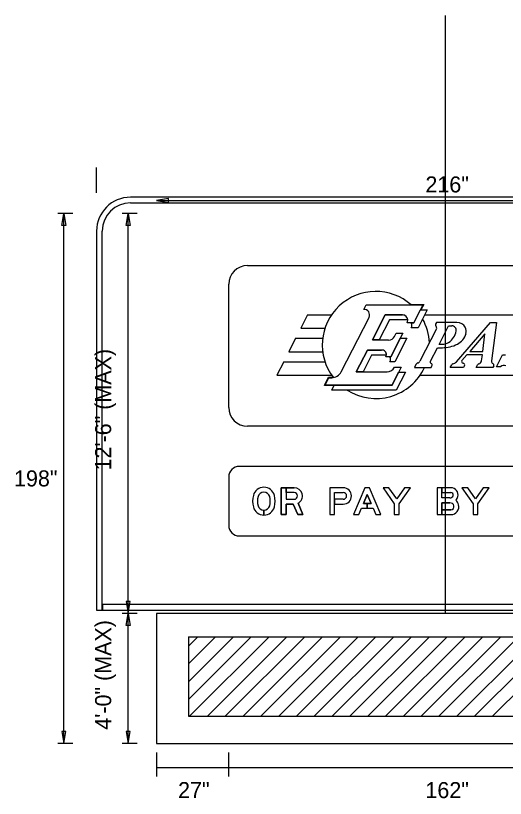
# Model space of a CAD drawing. Extents: x 10268312 to 10268706, y 2142548 to 2142786.
# Drawn here: x 10268428.63 to 10268450.13, y 2142751.91 to 2142786.29 of the extents above; entities that cross this region are included whole.
import ezdxf

# ---------------------------------------------------------------- set-up
doc = ezdxf.new("R2010")
doc.units = 0
for name, color, linetype in [('GSBWFill', 7, 'Continuous'), ('GSDims', 7, 'Continuous'), ('SignPanel', 7, 'Continuous'), ('TextMisc', 7, 'Continuous')]:
    doc.layers.add(name, color=color, linetype=linetype)

msp = doc.modelspace()

# ---------------------------------------------------------------- linework, layer by layer
at = {"layer": 'GSBWFill'}
for p, q in [((10268432.186, 2142778.502), (10268432.186, 2142779.616)), ((10268457.439, 2142778.317), (10268433.672, 2142778.317)), ((10268433.672, 2142778.069), (10268457.439, 2142778.069))]:
    msp.add_line(p, q, dxfattribs=at)
for points in [[(10268432.186, 2142776.831), (10268432.186, 2142760.182), (10268432.434, 2142760.182), (10268432.434, 2142776.831)], [(10268458.676, 2142760.43), (10268432.441, 2142760.43), (10268432.441, 2142760.182), (10268458.924, 2142760.182), (10268458.924, 2142760.182), (10268458.924, 2142776.831)]]:
    msp.add_lwpolyline(points, dxfattribs=at)
for radius in [1.485, 1.238]:
    msp.add_arc((10268433.672, 2142776.831), radius, 90, 180, dxfattribs=at)
at = {"layer": 'GSDims'}
for p, q in [((10268434.809, 2142778.177), (10268460.21, 2142778.177)), ((10268431.138, 2142777.605), (10268430.477, 2142777.605)), ((10268430.741, 2142754.321), (10268430.741, 2142777.605)), ((10268433.97, 2142777.605), (10268433.309, 2142777.605)), ((10268433.573, 2142760.024), (10268433.573, 2142777.605)), ((10268433.97, 2142760.024), (10268433.309, 2142760.024)), ((10268433.573, 2142754.321), (10268433.573, 2142760.024)), ((10268431.138, 2142754.321), (10268430.477, 2142754.321)), ((10268433.97, 2142754.321), (10268433.309, 2142754.321)), ((10268434.809, 2142753.924), (10268434.809, 2142752.865)), ((10268437.984, 2142753.924), (10268437.984, 2142752.865)), ((10268434.809, 2142753.262), (10268437.984, 2142753.262)), ((10268437.984, 2142753.262), (10268457.035, 2142753.262))]:
    msp.add_line(p, q, dxfattribs=at)
for points in [[(10268434.809, 2142778.177), (10268435.338, 2142778.089), (10268435.338, 2142778.265)], [(10268430.741, 2142777.605), (10268430.83, 2142777.075), (10268430.653, 2142777.075)], [(10268433.573, 2142777.605), (10268433.661, 2142777.075), (10268433.485, 2142777.075)], [(10268433.573, 2142760.024), (10268433.661, 2142760.553), (10268433.485, 2142760.553)], [(10268433.573, 2142760.024), (10268433.661, 2142759.495), (10268433.485, 2142759.495)], [(10268430.741, 2142754.321), (10268430.83, 2142754.85), (10268430.653, 2142754.85)], [(10268433.573, 2142754.321), (10268433.661, 2142754.85), (10268433.485, 2142754.85)]]:
    msp.add_lwpolyline(points, close=True, dxfattribs=at)
at = {"layer": 'SignPanel'}
for p, q in [((10268447.509, 2142760.024), (10268447.509, 2142786.291)), ((10268438.809, 2142775.312), (10268456.209, 2142775.312)), ((10268437.986, 2142769.081), (10268437.986, 2142774.489)), ((10268445.977, 2142773.609), (10268446.549, 2142773.609)), ((10268446.549, 2142773.609), (10268446.426, 2142773.366)), ((10268443.915, 2142773.389), (10268444.015, 2142773.587)), ((10268444.015, 2142773.587), (10268446.514, 2142773.587)), ((10268446.113, 2142772.8), (10268446.401, 2142773.366)), ((10268446.514, 2142773.587), (10268446.114, 2142772.801)), ((10268446.698, 2142773.366), (10268446.298, 2142772.58)), ((10268446.401, 2142773.366), (10268446.698, 2142773.366)), ((10268441.449, 2142773.146), (10268441.15, 2142772.558)), ((10268441.449, 2142773.146), (10268442.503, 2142773.146)), ((10268442.927, 2142770.644), (10268444.147, 2142773.037)), ((10268444.862, 2142773.146), (10268444.3, 2142772.044)), ((10268444.3, 2142772.044), (10268444.862, 2142773.146)), ((10268445.047, 2142772.925), (10268444.597, 2142772.044)), ((10268445.611, 2142773.146), (10268444.862, 2142773.146)), ((10268444.862, 2142773.146), (10268445.611, 2142773.146)), ((10268445.846, 2142772.925), (10268445.047, 2142772.925)), ((10268446.586, 2142773.146), (10268454.969, 2142773.146)), ((10268446.114, 2142772.801), (10268445.819, 2142772.801)), ((10268446.004, 2142772.8), (10268446.113, 2142772.8)), ((10268446.298, 2142772.58), (10268446.004, 2142772.58)), ((10268447.107, 2142772.815), (10268447.067, 2142772.737)), ((10268448.007, 2142772.815), (10268447.107, 2142772.815)), ((10268447.222, 2142771.852), (10268447.638, 2142772.668)), ((10268447.222, 2142771.852), (10268447.638, 2142772.668)), ((10268447.638, 2142772.668), (10268447.779, 2142772.668)), ((10268447.638, 2142772.668), (10268447.779, 2142772.668)), ((10268447.984, 2142771.089), (10268449.485, 2142772.815)), ((10268449.485, 2142772.815), (10268449.749, 2142772.815)), ((10268449.749, 2142772.815), (10268449.529, 2142771.124)), ((10268441.15, 2142772.558), (10268442.213, 2142772.558)), ((10268445.627, 2142772.338), (10268445.103, 2142771.309)), ((10268445.265, 2142772.204), (10268445.333, 2142772.338)), ((10268445.333, 2142772.338), (10268445.627, 2142772.338)), ((10268447.109, 2142772.537), (10268446.382, 2142771.109)), ((10268449.239, 2142772.308), (10268448.568, 2142771.536)), ((10268449.239, 2142772.308), (10268448.568, 2142771.536)), ((10268449.138, 2142771.536), (10268449.239, 2142772.308)), ((10268449.138, 2142771.536), (10268449.239, 2142772.308)), ((10268440.925, 2142772.117), (10268440.626, 2142771.529)), ((10268440.925, 2142772.117), (10268442.114, 2142772.117)), ((10268444.3, 2142772.044), (10268445.004, 2142772.044)), ((10268444.597, 2142772.044), (10268444.3, 2142772.044)), ((10268445.103, 2142771.309), (10268445.515, 2142772.117)), ((10268445.812, 2142772.117), (10268445.288, 2142771.088)), ((10268445.515, 2142772.117), (10268445.812, 2142772.117)), ((10268444.076, 2142771.603), (10268443.589, 2142770.647)), ((10268443.589, 2142770.647), (10268444.076, 2142771.603)), ((10268444.721, 2142771.603), (10268444.076, 2142771.603)), ((10268444.076, 2142771.603), (10268444.693, 2142771.601)), ((10268446.843, 2142771.109), (10268447.147, 2142771.705)), ((10268447.147, 2142771.705), (10268447.367, 2142771.705)), ((10268447.367, 2142771.852), (10268447.222, 2142771.852)), ((10268447.367, 2142771.852), (10268447.222, 2142771.852)), ((10268448.568, 2142771.536), (10268449.138, 2142771.536)), ((10268448.568, 2142771.536), (10268449.138, 2142771.536)), ((10268440.626, 2142771.529), (10268442.114, 2142771.529)), ((10268444.26, 2142771.382), (10268443.886, 2142770.647)), ((10268444.909, 2142771.38), (10268444.26, 2142771.382)), ((10268445.103, 2142771.309), (10268444.882, 2142771.309)), ((10268445.057, 2142771.309), (10268445.103, 2142771.309)), ((10268448.44, 2142771.389), (10268448.227, 2142771.145)), ((10268449.123, 2142771.389), (10268448.44, 2142771.389)), ((10268449.089, 2142771.124), (10268449.123, 2142771.389)), ((10268449.748, 2142770.868), (10268450.015, 2142771.392)), ((10268450.015, 2142771.392), (10268450.133, 2142771.392)), ((10268440.402, 2142771.088), (10268440.102, 2142770.5)), ((10268440.402, 2142771.088), (10268442.213, 2142771.088)), ((10268445.288, 2142771.088), (10268445.067, 2142771.088)), ((10268445.558, 2142770.845), (10268445.157, 2142770.06)), ((10268445.264, 2142770.845), (10268445.558, 2142770.845)), ((10268446.203, 2142770.961), (10268446.137, 2142770.831)), ((10268446.872, 2142770.831), (10268446.912, 2142770.91)), ((10268447.714, 2142770.831), (10268447.778, 2142770.957)), ((10268448.345, 2142770.916), (10268448.302, 2142770.831)), ((10268448.848, 2142770.831), (10268448.913, 2142770.959)), ((10268449.621, 2142770.907), (10268449.583, 2142770.831)), ((10268449.927, 2142770.868), (10268449.748, 2142770.868)), ((10268440.102, 2142770.5), (10268442.503, 2142770.5)), ((10268443.589, 2142770.647), (10268444.938, 2142770.647)), ((10268443.886, 2142770.647), (10268443.589, 2142770.647)), ((10268445.157, 2142770.06), (10268445.445, 2142770.625)), ((10268445.742, 2142770.625), (10268445.342, 2142769.839)), ((10268445.445, 2142770.625), (10268445.742, 2142770.625)), ((10268446.137, 2142770.831), (10268446.872, 2142770.831)), ((10268446.391, 2142770.5), (10268453.621, 2142770.5)), ((10268448.302, 2142770.831), (10268447.714, 2142770.831)), ((10268449.583, 2142770.831), (10268448.848, 2142770.831)), ((10268442.187, 2142770.04), (10268442.373, 2142770.406)), ((10268442.218, 2142770.06), (10268442.385, 2142770.387)), ((10268442.373, 2142770.406), (10268442.508, 2142770.406)), ((10268442.385, 2142770.387), (10268442.508, 2142770.387)), ((10268442.615, 2142770.04), (10268442.187, 2142770.04)), ((10268445.157, 2142770.06), (10268442.218, 2142770.06)), ((10268442.512, 2142769.839), (10268442.624, 2142770.06)), ((10268445.342, 2142769.839), (10268442.512, 2142769.839)), ((10268442.624, 2142770.06), (10268445.157, 2142770.06)), ((10268456.209, 2142768.258), (10268438.809, 2142768.258)), ((10268456.562, 2142766.492), (10268438.457, 2142766.492)), ((10268437.986, 2142766.021), (10268437.986, 2142763.905)), ((10268442.635, 2142765.339), (10268443.017, 2142765.339)), ((10268442.635, 2142765.339), (10268443.017, 2142765.339)), ((10268442.635, 2142765.339), (10268443.017, 2142765.339)), ((10268442.635, 2142764.834), (10268443.017, 2142764.834)), ((10268439.53, 2142764.354), (10268439.53, 2142764.566)), ((10268439.53, 2142764.566), (10268439.53, 2142764.354)), ((10268439.53, 2142764.354), (10268439.53, 2142764.566)), ((10268439.53, 2142764.566), (10268439.53, 2142764.354)), ((10268447.139, 2142764.375), (10268447.744, 2142764.375)), ((10268438.457, 2142763.434), (10268456.558, 2142763.434)), ((10268460.21, 2142760.024), (10268434.809, 2142760.024)), ((10268434.809, 2142760.024), (10268434.809, 2142754.321)), ((10268434.809, 2142754.321), (10268460.21, 2142754.321))]:
    msp.add_line(p, q, dxfattribs=at)
for points in [[(10268440.863, 2142765.551), (10268440.295, 2142765.551), (10268440.295, 2142764.375), (10268440.506, 2142764.375), (10268440.506, 2142764.834), (10268440.818, 2142764.834), (10268441.017, 2142764.375), (10268441.247, 2142764.375), (10268441.031, 2142764.875)], [(10268441.031, 2142764.875), (10268441.247, 2142764.375), (10268441.017, 2142764.375), (10268440.818, 2142764.834), (10268440.506, 2142764.834), (10268440.506, 2142764.375), (10268440.295, 2142764.375), (10268440.295, 2142765.551), (10268440.506, 2142765.551), (10268440.506, 2142765.045), (10268440.863, 2142765.045)], [(10268441.031, 2142764.875), (10268441.247, 2142764.375), (10268441.017, 2142764.375), (10268440.818, 2142764.834), (10268440.506, 2142764.834), (10268440.506, 2142764.375), (10268440.295, 2142764.375), (10268440.295, 2142765.551), (10268440.506, 2142765.551), (10268440.506, 2142765.045), (10268440.863, 2142765.045)], [(10268440.506, 2142765.339), (10268440.506, 2142765.551), (10268440.863, 2142765.551)], [(10268440.506, 2142765.339), (10268440.506, 2142765.551), (10268440.863, 2142765.551)], [(10268443.017, 2142765.551), (10268442.423, 2142765.551), (10268442.423, 2142764.375), (10268442.635, 2142764.375), (10268442.635, 2142764.834)], [(10268443.017, 2142765.551), (10268442.423, 2142765.551), (10268442.423, 2142764.375), (10268442.635, 2142764.375), (10268442.635, 2142765.339)], [(10268443.017, 2142765.551), (10268442.423, 2142765.551), (10268442.423, 2142764.375), (10268442.635, 2142764.375), (10268442.635, 2142765.339)], [(10268447.744, 2142765.551), (10268447.139, 2142765.551), (10268447.139, 2142764.375)], [(10268447.699, 2142765.104), (10268447.35, 2142765.104), (10268447.35, 2142765.551), (10268447.139, 2142765.551), (10268447.139, 2142764.375), (10268447.35, 2142764.375)], [(10268447.699, 2142765.104), (10268447.35, 2142765.104), (10268447.35, 2142765.551), (10268447.139, 2142765.551), (10268447.139, 2142764.375), (10268447.35, 2142764.375)], [(10268447.744, 2142765.551), (10268447.351, 2142765.551), (10268447.351, 2142765.339), (10268447.744, 2142765.339)], [(10268447.744, 2142765.551), (10268447.351, 2142765.551), (10268447.351, 2142765.339), (10268447.744, 2142765.339)], [(10268440.863, 2142765.339), (10268440.506, 2142765.339), (10268440.506, 2142765.045), (10268440.863, 2142765.045)], [(10268440.863, 2142765.339), (10268440.506, 2142765.339)], [(10268440.863, 2142765.339), (10268440.506, 2142765.339)], [(10268443.017, 2142765.045), (10268442.635, 2142765.045), (10268442.635, 2142765.339)], [(10268443.017, 2142765.045), (10268442.635, 2142765.045), (10268442.635, 2142764.834), (10268443.017, 2142764.834)], [(10268443.017, 2142765.045), (10268442.635, 2142765.045), (10268442.635, 2142764.834), (10268443.017, 2142764.834)], [(10268447.699, 2142765.104), (10268447.35, 2142765.104), (10268447.35, 2142765.339), (10268447.744, 2142765.339)], [(10268447.699, 2142764.892), (10268447.35, 2142764.892), (10268447.35, 2142764.587), (10268447.744, 2142764.587)], [(10268447.35, 2142764.375), (10268447.35, 2142764.892), (10268447.699, 2142764.892)], [(10268447.35, 2142764.375), (10268447.35, 2142764.892), (10268447.699, 2142764.892)], [(10268447.744, 2142764.587), (10268447.351, 2142764.587), (10268447.351, 2142764.375), (10268447.744, 2142764.375)], [(10268447.744, 2142764.587), (10268447.351, 2142764.587), (10268447.351, 2142764.375), (10268447.744, 2142764.375)]]:
    msp.add_lwpolyline(points, dxfattribs=at)
for points in [[(10268443.815, 2142764.651), (10268444.324, 2142764.651), (10268444.44, 2142764.375), (10268444.669, 2142764.375), (10268444.175, 2142765.551), (10268443.964, 2142765.551), (10268443.47, 2142764.375), (10268443.699, 2142764.375)], [(10268444.235, 2142764.863), (10268444.07, 2142764.863), (10268444.07, 2142764.651), (10268444.324, 2142764.651), (10268444.44, 2142764.375), (10268444.669, 2142764.375), (10268444.175, 2142765.551), (10268443.964, 2142765.551), (10268443.47, 2142764.375), (10268443.699, 2142764.375), (10268443.815, 2142764.651), (10268444.07, 2142764.651), (10268444.07, 2142764.863), (10268443.904, 2142764.863), (10268444.07, 2142765.256)], [(10268444.235, 2142764.863), (10268444.07, 2142764.863), (10268444.07, 2142764.651), (10268444.324, 2142764.651), (10268444.44, 2142764.375), (10268444.669, 2142764.375), (10268444.175, 2142765.551), (10268443.964, 2142765.551), (10268443.47, 2142764.375), (10268443.699, 2142764.375), (10268443.815, 2142764.651), (10268444.07, 2142764.651), (10268444.07, 2142764.863), (10268443.904, 2142764.863), (10268444.07, 2142765.256)], [(10268445.469, 2142764.851), (10268445.963, 2142765.551), (10268445.704, 2142765.551), (10268445.363, 2142765.068), (10268445.022, 2142765.551), (10268444.763, 2142765.551), (10268445.257, 2142764.851), (10268445.257, 2142764.375), (10268445.469, 2142764.375)], [(10268445.469, 2142764.851), (10268445.963, 2142765.551), (10268445.704, 2142765.551), (10268445.363, 2142765.068), (10268445.022, 2142765.551), (10268444.763, 2142765.551), (10268445.257, 2142764.851), (10268445.257, 2142764.375), (10268445.469, 2142764.375)], [(10268445.469, 2142764.851), (10268445.963, 2142765.551), (10268445.704, 2142765.551), (10268445.363, 2142765.068), (10268445.022, 2142765.551), (10268444.763, 2142765.551), (10268445.257, 2142764.851), (10268445.257, 2142764.375), (10268445.469, 2142764.375)], [(10268448.926, 2142764.851), (10268449.42, 2142765.551), (10268449.161, 2142765.551), (10268448.82, 2142765.068), (10268448.48, 2142765.551), (10268448.221, 2142765.551), (10268448.715, 2142764.851), (10268448.715, 2142764.375), (10268448.926, 2142764.375)], [(10268448.926, 2142764.851), (10268449.42, 2142765.551), (10268449.161, 2142765.551), (10268448.82, 2142765.068), (10268448.48, 2142765.551), (10268448.221, 2142765.551), (10268448.715, 2142764.851), (10268448.715, 2142764.375), (10268448.926, 2142764.375)], [(10268448.926, 2142764.851), (10268449.42, 2142765.551), (10268449.161, 2142765.551), (10268448.82, 2142765.068), (10268448.48, 2142765.551), (10268448.221, 2142765.551), (10268448.715, 2142764.851), (10268448.715, 2142764.375), (10268448.926, 2142764.375)], [(10268444.235, 2142764.863), (10268444.07, 2142765.256), (10268443.904, 2142764.863)]]:
    msp.add_lwpolyline(points, close=True, dxfattribs=at)
for centre, radius, start, end in [((10268438.809, 2142774.489), 0.823, 90, 180), ((10268444.447, 2142771.823), 2.351, 48.5904, 217.4727), ((10268443.931, 2142773.147), 0.242, 332.9998, 93.8045), ((10268445.611, 2142772.91), 0.235, 332.2089, 90), ((10268445.611, 2142772.91), 0.235, 3.5833, 90), ((10268444.447, 2142771.823), 2.351, 2.4236, 29.2771), ((10268445.796, 2142772.69), 0.235, 332.2089, 27.9127), ((10268447.132, 2142772.703), 0.0735, 152.9784, 231.1602), ((10268447.031, 2142772.577), 0.0882, 333.0027, 51.1602), ((10268447.779, 2142772.47), 0.198, 351.076, 90), ((10268447.779, 2142772.47), 0.198, 351.076, 90), ((10268448.007, 2142772.396), 0.419, 29.4315, 90), ((10268448.051, 2142772.421), 0.367, 344.7074, 29.4315), ((10268447.249, 2142772.553), 0.735, 302.4206, 351.076), ((10268447.249, 2142772.553), 0.735, 302.4206, 351.076), ((10268447.697, 2142772.518), 0.735, 296.6431, 344.7074), ((10268445.003, 2142772.337), 0.294, 270, 332.9883), ((10268447.367, 2142772.367), 0.514, 270, 302.4206), ((10268447.367, 2142772.367), 0.514, 270, 302.4206), ((10268444.721, 2142771.411), 0.191, 350.3502, 98.3344), ((10268444.721, 2142771.411), 0.191, 327.421, 90), ((10268447.367, 2142773.175), 1.47, 270, 296.6431), ((10268444.906, 2142771.191), 0.191, 327.421, 37.9799), ((10268444.938, 2142771.015), 0.367, 270, 332.5096), ((10268446.334, 2142770.894), 0.147, 106.4317, 152.9742), ((10268446.251, 2142771.176), 0.147, 286.4317, 332.9959), ((10268446.909, 2142771.076), 0.0735, 152.9884, 244.7832), ((10268446.846, 2142770.943), 0.0735, 333.0239, 64.7832), ((10268447.843, 2142770.923), 0.0735, 102.7162, 153.0239), ((10268447.762, 2142771.282), 0.294, 282.7162, 318.9966), ((10268448.283, 2142771.096), 0.0735, 138.9824, 268.6869), ((10268448.279, 2142770.949), 0.0735, 332.9784, 88.6869), ((10268448.978, 2142770.925), 0.0735, 99.2397, 153.0239), ((10268448.943, 2142771.143), 0.147, 279.2397, 352.5632), ((10268449.646, 2142771.109), 0.118, 172.5884, 241.8673), ((10268449.556, 2142770.94), 0.0735, 332.9784, 61.8673), ((10268450.068, 2142770.718), 0.206, 64.3795, 133.1892), ((10268442.508, 2142770.857), 0.47, 270, 332.9991), ((10268444.447, 2142771.823), 2.351, 237.5383, 335.047), ((10268442.508, 2142770.857), 0.451, 270, 277.5038), ((10268438.809, 2142769.081), 0.823, 180, 270), ((10268438.457, 2142766.021), 0.47, 90, 180), ((10268439.53, 2142765.095), 0.477, 14.9618, 165.0382), ((10268439.53, 2142765.095), 0.477, 14.9618, 165.0382), ((10268439.53, 2142765.095), 0.477, 14.9618, 165.0382), ((10268439.53, 2142765.095), 0.265, 14.9618, 165.0382), ((10268439.53, 2142765.095), 0.265, 14.9618, 165.0382), ((10268439.53, 2142765.095), 0.265, 14.9618, 165.0382), ((10268440.863, 2142765.192), 0.359, 297.837, 90), ((10268440.863, 2142765.192), 0.359, 297.837, 90), ((10268440.863, 2142765.192), 0.359, 297.837, 90), ((10268443.017, 2142765.192), 0.359, 270, 90), ((10268443.017, 2142765.192), 0.359, 270, 90), ((10268443.017, 2142765.192), 0.359, 270, 90), ((10268447.744, 2142765.239), 0.312, 345.5225, 90), ((10268447.744, 2142765.239), 0.312, 345.5225, 90), ((10268447.744, 2142765.239), 0.312, 345.5225, 90), ((10268440.024, 2142764.963), 0.988, 165.0382, 194.9618), ((10268440.024, 2142764.963), 0.988, 165.0382, 194.9618), ((10268440.024, 2142764.963), 0.988, 165.0382, 194.9618), ((10268440.024, 2142764.963), 0.776, 165.0382, 194.9618), ((10268440.024, 2142764.963), 0.776, 165.0382, 194.9618), ((10268440.024, 2142764.963), 0.776, 165.0382, 194.9618), ((10268439.036, 2142764.963), 0.776, 345.0382, 14.9618), ((10268439.036, 2142764.963), 0.776, 345.0382, 14.9618), ((10268439.036, 2142764.963), 0.776, 345.0382, 14.9618), ((10268439.036, 2142764.963), 0.988, 345.0382, 14.9618), ((10268439.036, 2142764.963), 0.988, 345.0382, 14.9618), ((10268439.036, 2142764.963), 0.988, 345.0382, 14.9618), ((10268440.863, 2142765.192), 0.147, 270, 90), ((10268440.863, 2142765.192), 0.147, 270, 90), ((10268440.863, 2142765.192), 0.147, 270, 90), ((10268443.017, 2142765.192), 0.147, 270, 90), ((10268443.017, 2142765.192), 0.147, 270, 90), ((10268443.017, 2142765.192), 0.147, 270, 90), ((10268447.699, 2142765.251), 0.147, 270, 345.5225), ((10268447.699, 2142765.251), 0.147, 270, 345.5225), ((10268447.699, 2142765.251), 0.147, 270, 345.5225), ((10268447.744, 2142765.239), 0.1, 345.5225, 90), ((10268447.744, 2142765.239), 0.1, 345.5225, 90), ((10268447.744, 2142765.239), 0.1, 345.5225, 90), ((10268447.699, 2142765.251), 0.359, 316.7114, 345.5225), ((10268447.699, 2142765.251), 0.359, 316.7114, 345.5225), ((10268447.699, 2142765.251), 0.359, 316.7114, 345.5225), ((10268447.699, 2142764.71), 0.394, 14.4775, 48.4921), ((10268447.699, 2142764.71), 0.394, 14.4775, 48.4921), ((10268447.699, 2142764.71), 0.394, 14.4775, 48.4921), ((10268439.53, 2142764.831), 0.477, 194.9618, 345.0382), ((10268439.53, 2142764.831), 0.477, 194.9618, 270), ((10268439.53, 2142764.831), 0.477, 194.9618, 270), ((10268439.53, 2142764.831), 0.265, 194.9618, 345.0382), ((10268439.53, 2142764.831), 0.265, 194.9618, 270), ((10268439.53, 2142764.831), 0.265, 194.9618, 270), ((10268439.53, 2142764.831), 0.265, 270.0127, 345.0382), ((10268439.53, 2142764.831), 0.265, 270.0127, 345.0382), ((10268439.53, 2142764.831), 0.477, 270.0071, 345.0382), ((10268439.53, 2142764.831), 0.477, 270.0071, 345.0382), ((10268447.699, 2142764.71), 0.182, 14.4775, 90), ((10268447.699, 2142764.71), 0.182, 14.4775, 90), ((10268447.699, 2142764.71), 0.182, 14.4775, 90), ((10268447.744, 2142764.722), 0.347, 270, 14.4775), ((10268447.744, 2142764.722), 0.347, 270, 14.4775), ((10268447.744, 2142764.722), 0.347, 270, 14.4775), ((10268447.744, 2142764.722), 0.135, 270, 14.4775), ((10268447.744, 2142764.722), 0.135, 270, 14.4775), ((10268447.744, 2142764.722), 0.135, 270, 14.4775), ((10268438.457, 2142763.905), 0.47, 180, 270)]:
    msp.add_arc(centre, radius, start, end, dxfattribs=at)
at = {"layer": 'TextMisc'}
for p, q in [((10268436.22, 2142758.593), (10268436.63, 2142759.002)), ((10268436.22, 2142757.812), (10268437.412, 2142759.002)), ((10268436.22, 2142757.032), (10268438.194, 2142759.002)), ((10268436.22, 2142756.251), (10268438.976, 2142759.002)), ((10268436.22, 2142759.002), (10268458.799, 2142759.002)), ((10268436.22, 2142759.002), (10268436.22, 2142755.519)), ((10268436.268, 2142755.519), (10268439.759, 2142759.002)), ((10268437.05, 2142755.519), (10268440.541, 2142759.002)), ((10268437.833, 2142755.519), (10268441.323, 2142759.002)), ((10268438.615, 2142755.519), (10268442.106, 2142759.002)), ((10268439.397, 2142755.519), (10268442.888, 2142759.002)), ((10268440.18, 2142755.519), (10268443.67, 2142759.002)), ((10268440.962, 2142755.519), (10268444.453, 2142759.002)), ((10268441.744, 2142755.519), (10268445.235, 2142759.002)), ((10268442.527, 2142755.519), (10268446.017, 2142759.002)), ((10268443.309, 2142755.519), (10268446.8, 2142759.002)), ((10268444.091, 2142755.519), (10268447.582, 2142759.002)), ((10268444.874, 2142755.519), (10268448.364, 2142759.002)), ((10268445.656, 2142755.519), (10268449.146, 2142759.002)), ((10268446.438, 2142755.519), (10268449.929, 2142759.002)), ((10268447.22, 2142755.519), (10268450.711, 2142759.002)), ((10268448.003, 2142755.519), (10268451.493, 2142759.002)), ((10268448.785, 2142755.519), (10268452.276, 2142759.002)), ((10268449.567, 2142755.519), (10268453.058, 2142759.002)), ((10268436.22, 2142755.519), (10268458.799, 2142755.519))]:
    msp.add_line(p, q, dxfattribs=at)

# ---------------------------------------------------------------- texts
at = {"layer": 'GSDims'}
for s, p in [('216"', (10268446.623, 2142778.524)), ('27"', (10268435.763, 2142751.918)), ('162"', (10268446.623, 2142751.918))]:
    msp.add_text(s, height=0.7056, dxfattribs=at).set_placement(p)
for s, height, rotation, p in [('12\'-6" (MAX)', 0.70558, 90, (10268432.825, 2142766.313)), ('198"', 0.7056, 360, (10268428.559, 2142765.61)), ('4\'-0" (MAX)', 0.70558, 90, (10268432.825, 2142754.924))]:
    msp.add_text(s, height=height, rotation=rotation, dxfattribs=at).set_placement(p)

doc.saveas('drawing.dxf')
